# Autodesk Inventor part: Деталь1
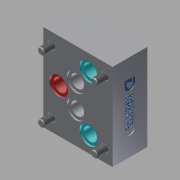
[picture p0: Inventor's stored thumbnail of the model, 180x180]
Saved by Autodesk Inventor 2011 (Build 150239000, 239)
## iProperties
Created: 2014-06
Part Number: Деталь1
Document SubType Name: Modeling
Designer: Храмов
Density: 1 g/cm^3
Author: Храмов
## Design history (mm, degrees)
derived "19502221.iam"
node "Твердое тело1"
node "1950220-05.ipt:1"
sketch "Cylinder head screw DIN 912 M6x25.ipt:1"
sketch "Cylinder head screw DIN 912 M6x25.ipt:2"
sketch "Cylinder head screw DIN 912 M6x25.ipt:3"
sketch "Cylinder head screw DIN 912 M6x25.ipt:4"
